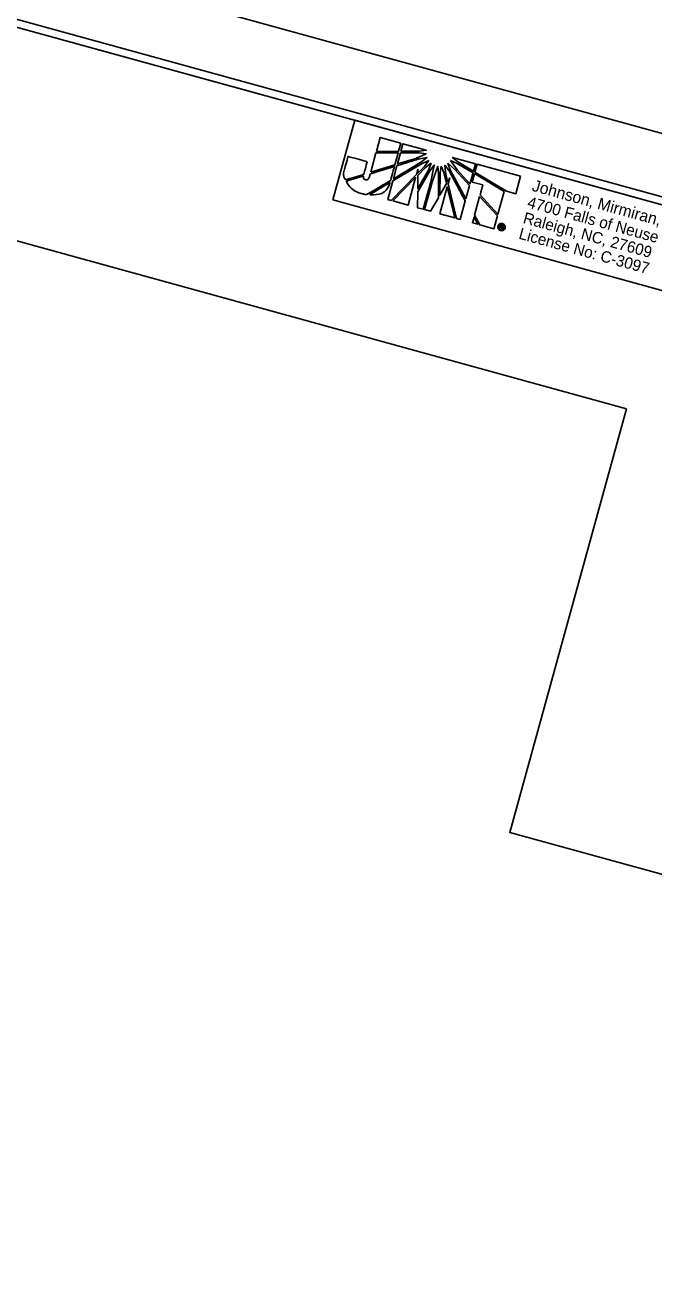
# Model space of a CAD drawing. Extents: x 1641063 to 2864602, y 841295 to 973236.
# Drawn here: x 1642637.9 to 1642843.9, y 842046.5 to 842457.9 of the extents above; entities that cross this region are included whole.
import ezdxf

# ---------------------------------------------------------------- set-up
doc = ezdxf.new("R2010")
doc.units = 0
for name, color, linetype in [('Old_Level_4', 7, 'Continuous'), ('Prop CMT Concrete Structures', 7, 'Continuous'), ('Prop CMT Guardrail Widen Shoulder', 7, 'Continuous'), ('Prop Dimension Text', 7, 'Continuous'), ('Prop PHM Wetland Impact Area Boundary Line', 7, 'Continuous')]:
    doc.layers.add(name, color=color, linetype=linetype)

msp = doc.modelspace()

# ---------------------------------------------------------------- linework, layer by layer
at = {"layer": 'Old_Level_4'}
msp.add_lwpolyline([(1641192.11, 841741.99), (1642815.27, 841295.31), (1643105.8, 842351.06), (1641482.64, 842797.74)], close=True, dxfattribs=at)
msp.add_lwpolyline([(1641192.11, 841741.99), (1642815.27, 841295.31), (1643105.8, 842351.06), (1641482.64, 842797.74)], close=True, dxfattribs=at)
at = {"layer": 'Prop CMT Concrete Structures'}
for points in [[(1643083.47, 842333.88), (1641637.2, 842731.89), (1641358.6, 841719.52), (1642804.85, 841321.52)], [(1641358.6, 841719.52), (1641637.16, 842731.87), (1642890.57, 842386.98), (1642850.76, 842242.29), (1643043.63, 842189.2), (1642804.85, 841321.52)]]:
    msp.add_lwpolyline(points, close=True, dxfattribs=at)
at = {"layer": 'Prop CMT Guardrail Widen Shoulder'}
for p, q in [((1642754.19, 842421.06), (1642752.96, 842416.57)), ((1642760.96, 842419.21), (1642754.19, 842421.06)), ((1642752.96, 842416.57), (1642760.24, 842416.59)), ((1642760.24, 842416.59), (1642760.96, 842419.21)), ((1642761.67, 842419.05), (1642761.01, 842416.62)), ((1642761.01, 842416.62), (1642767.12, 842416.63)), ((1642769.3, 842416.96), (1642761.67, 842419.05)), ((1642767.12, 842416.63), (1642769.3, 842416.96)), ((1642752.82, 842416.06), (1642751.09, 842409.75)), ((1642760.11, 842416.1), (1642752.82, 842416.06)), ((1642767.91, 842412.64), (1642758.34, 842406.9)), ((1642758.54, 842407.62), (1642767.72, 842413.09)), ((1642759.03, 842412.18), (1642760.11, 842416.1)), ((1642766.59, 842413.97), (1642759.7, 842411.84)), ((1642760.87, 842416.1), (1642759.86, 842412.43)), ((1642759.86, 842412.43), (1642765.83, 842414.26)), ((1642766.97, 842416.11), (1642760.87, 842416.1)), ((1642765.83, 842414.26), (1642769.26, 842415.77)), ((1642769.53, 842414.56), (1642766.59, 842413.97)), ((1642769.26, 842415.77), (1642766.97, 842416.11)), ((1642767.72, 842413.09), (1642769.53, 842414.56)), ((1642770.09, 842413.53), (1642767.91, 842412.64)), ((1642768.66, 842411.59), (1642770.09, 842413.53)), ((1642770.89, 842412.66), (1642769.08, 842411.31)), ((1642770.13, 842410.63), (1642770.89, 842412.66)), ((1642776.35, 842412.69), (1642777.15, 842410.47)), ((1642778.61, 842410.67), (1642776.35, 842412.69)), ((1642777.23, 842413.58), (1642779.44, 842410.48)), ((1642779.25, 842412.74), (1642777.23, 842413.58)), ((1642785.42, 842412.5), (1642777.92, 842414.59)), ((1642777.92, 842414.59), (1642779.58, 842413.18)), ((1642784.61, 842409.55), (1642779.25, 842412.74)), ((1642779.58, 842413.18), (1642784.75, 842410.07)), ((1642784.75, 842410.07), (1642785.42, 842412.5)), ((1642785.95, 842412.39), (1642785.24, 842409.78)), ((1642800.19, 842408.49), (1642785.95, 842412.39)), ((1642751.09, 842409.75), (1642759.03, 842412.18)), ((1642757.78, 842400.45), (1642766.05, 842408.94)), ((1642759.7, 842411.84), (1642758.54, 842407.62)), ((1642766.05, 842408.94), (1642766.54, 842410.72)), ((1642770.41, 842410.14), (1642766.49, 842403.35)), ((1642766.52, 842404.35), (1642770.13, 842410.63)), ((1642766.55, 842408.71), (1642766.52, 842404.35)), ((1642766.54, 842409.4), (1642768.66, 842411.59)), ((1642766.54, 842410.72), (1642766.54, 842409.4)), ((1642769.08, 842411.31), (1642766.55, 842408.71)), ((1642771.93, 842412.06), (1642770.41, 842410.14)), ((1642770.75, 842406.64), (1642771.93, 842412.06)), ((1642773.04, 842411.75), (1642771.23, 842406.5)), ((1642773.34, 842409.34), (1642773.04, 842411.75)), ((1642773.25, 842401.37), (1642773.34, 842409.34)), ((1642773.84, 842409.53), (1642773.72, 842402.21)), ((1642774.21, 842411.76), (1642773.84, 842409.53)), ((1642775.05, 842409.68), (1642774.21, 842411.76)), ((1642775.93, 842406.02), (1642775.05, 842409.68)), ((1642775.34, 842412.09), (1642775.57, 842409.7)), ((1642776.76, 842410.22), (1642775.34, 842412.09)), ((1642775.57, 842409.7), (1642776.28, 842406.61)), ((1642782.04, 842400.34), (1642776.76, 842410.22)), ((1642777.15, 842410.47), (1642782.23, 842401.04)), ((1642783.42, 842405.37), (1642778.61, 842410.67)), ((1642779.44, 842410.48), (1642783.58, 842405.98)), ((1642783.58, 842405.98), (1642784.61, 842409.55)), ((1642785.09, 842409.25), (1642784.35, 842406.53)), ((1642785.11, 842409.3), (1642785.09, 842409.25)), ((1642794.78, 842403.43), (1642785.11, 842409.3)), ((1642785.24, 842409.78), (1642785.22, 842409.7)), ((1642785.22, 842409.7), (1642795.56, 842403.49)), ((1642798.59, 842402.66), (1642800.19, 842408.49)), ((1642758.34, 842406.9), (1642756.66, 842400.76)), ((1642765.78, 842407.96), (1642758.3, 842400.31)), ((1642763.35, 842398.92), (1642765.78, 842407.96)), ((1642768.28, 842397.61), (1642770.75, 842406.64)), ((1642771.23, 842406.5), (1642768.76, 842397.48)), ((1642773.72, 842402.21), (1642775.93, 842406.02)), ((1642776.19, 842404.91), (1642773.78, 842396.1)), ((1642778.62, 842394.77), (1642776.19, 842404.91)), ((1642776.28, 842406.61), (1642777, 842407.86)), ((1642777, 842407.86), (1642776.46, 842405.88)), ((1642776.46, 842405.88), (1642779.17, 842394.58)), ((1642782.23, 842401.04), (1642783.42, 842405.37)), ((1642784.35, 842406.53), (1642787.82, 842405.57)), ((1642787.82, 842405.57), (1642786.93, 842402.32)), ((1642756.66, 842400.76), (1642757.78, 842400.45)), ((1642758.3, 842400.31), (1642763.35, 842398.92)), ((1642766.49, 842403.35), (1642766.42, 842398.12)), ((1642770.64, 842396.96), (1642773.25, 842401.37)), ((1642780.37, 842394.26), (1642782.04, 842400.34)), ((1642786.78, 842401.76), (1642785.12, 842395.71)), ((1642792.58, 842395.43), (1642786.78, 842401.76)), ((1642786.93, 842402.32), (1642792.73, 842395.95)), ((1642792.73, 842395.95), (1642794.78, 842403.43)), ((1642795.56, 842403.49), (1642798.59, 842402.66)), ((1642766.42, 842398.12), (1642768.28, 842397.61)), ((1642768.76, 842397.48), (1642770.64, 842396.96)), ((1642773.78, 842396.1), (1642778.62, 842394.77)), ((1642779.17, 842394.58), (1642780.37, 842394.26)), ((1642784.94, 842395.05), (1642784.41, 842393.15)), ((1642784.41, 842393.15), (1642786.17, 842392.67)), ((1642786.17, 842392.67), (1642784.94, 842395.05)), ((1642785.12, 842395.71), (1642786.84, 842392.48)), ((1642786.84, 842392.48), (1642791.43, 842391.22)), ((1642791.43, 842391.22), (1642792.58, 842395.43)), ((1642793.39, 842391.37), (1642793.67, 842392.41)), ((1642793.67, 842392.41), (1642794.1, 842392.29)), ((1642793.85, 842392.15), (1642793.79, 842391.9)), ((1642793.79, 842391.9), (1642793.98, 842391.85)), ((1642794.04, 842392.1), (1642793.85, 842392.15)), ((1642793.98, 842391.85), (1642793.92, 842391.66)), ((1642793.92, 842391.66), (1642793.98, 842391.85)), ((1642793.98, 842391.85), (1642793.99, 842391.85)), ((1642794.1, 842392.29), (1642794.04, 842392.1)), ((1642794.04, 842392.1), (1642794.1, 842392.29)), ((1642794.07, 842392.09), (1642794.04, 842392.1)), ((1642794.1, 842392.29), (1642794.16, 842392.28)), ((1642794.26, 842392.91), (1642794.21, 842392.69)), ((1642794.21, 842392.69), (1642794.26, 842392.91)), ((1642793.62, 842391.31), (1642793.39, 842391.37)), ((1642793.74, 842391.71), (1642793.62, 842391.31)), ((1642793.7, 842390.85), (1642793.64, 842390.63)), ((1642793.64, 842390.63), (1642793.7, 842390.85)), ((1642793.65, 842390.63), (1642793.64, 842390.63)), ((1642793.7, 842390.85), (1642793.71, 842390.85)), ((1642793.92, 842391.66), (1642793.74, 842391.71)), ((1642793.93, 842391.66), (1642793.92, 842391.66))]:
    msp.add_line(p, q, dxfattribs=at)
msp.add_lwpolyline([(1642738.73, 842400.68), (1642883.38, 842360.88), (1642890.57, 842386.98), (1642745.92, 842426.79)], close=True, dxfattribs=at)
for points in [[(1642752.96, 842416.57), (1642760.24, 842416.59), (1642760.96, 842419.21), (1642754.19, 842421.06), (1642752.96, 842416.57)], [(1642767.12, 842416.63), (1642769.3, 842416.96), (1642761.67, 842419.05), (1642761.01, 842416.62), (1642767.12, 842416.63)], [(1642751.09, 842409.75), (1642759.03, 842412.18), (1642760.11, 842416.1), (1642752.82, 842416.06), (1642751.09, 842409.75)], [(1642770.09, 842413.53), (1642767.91, 842412.64), (1642758.34, 842406.9), (1642756.66, 842400.76), (1642757.78, 842400.45), (1642766.05, 842408.94), (1642766.54, 842410.72), (1642766.54, 842409.4), (1642768.66, 842411.59), (1642770.09, 842413.53)], [(1642759.7, 842411.84), (1642758.54, 842407.62), (1642767.72, 842413.09), (1642769.53, 842414.56), (1642766.59, 842413.97), (1642759.7, 842411.84)], [(1642760.87, 842416.1), (1642759.86, 842412.43), (1642765.83, 842414.26), (1642769.26, 842415.77), (1642766.97, 842416.11), (1642760.87, 842416.1)], [(1642770.89, 842412.66), (1642769.08, 842411.31), (1642766.55, 842408.71), (1642766.52, 842404.35), (1642770.13, 842410.63), (1642770.89, 842412.66)], [(1642776.35, 842412.69), (1642777.15, 842410.47), (1642782.23, 842401.04), (1642783.42, 842405.37), (1642778.61, 842410.67), (1642776.35, 842412.69)], [(1642777.23, 842413.58), (1642779.44, 842410.48), (1642783.58, 842405.98), (1642784.61, 842409.55), (1642779.25, 842412.74), (1642777.23, 842413.58)], [(1642779.58, 842413.18), (1642784.75, 842410.07), (1642785.42, 842412.5), (1642777.92, 842414.59), (1642779.58, 842413.18)], [(1642800.19, 842408.49), (1642785.95, 842412.39), (1642785.24, 842409.78), (1642785.22, 842409.7), (1642795.56, 842403.49), (1642798.59, 842402.66), (1642800.19, 842408.49)], [(1642770.41, 842410.14), (1642766.49, 842403.35), (1642766.42, 842398.12), (1642768.28, 842397.61), (1642770.75, 842406.64), (1642771.93, 842412.06), (1642770.41, 842410.14)], [(1642773.04, 842411.75), (1642771.23, 842406.5), (1642768.76, 842397.48), (1642770.64, 842396.96), (1642773.25, 842401.37), (1642773.34, 842409.34), (1642773.04, 842411.75)], [(1642774.21, 842411.76), (1642773.84, 842409.53), (1642773.72, 842402.21), (1642775.93, 842406.02), (1642775.05, 842409.68), (1642774.21, 842411.76)], [(1642775.34, 842412.09), (1642775.57, 842409.7), (1642776.28, 842406.61), (1642777, 842407.86), (1642776.46, 842405.88), (1642779.17, 842394.58), (1642780.37, 842394.26), (1642782.04, 842400.34), (1642776.76, 842410.22), (1642775.34, 842412.09)], [(1642785.11, 842409.3), (1642785.09, 842409.25), (1642784.35, 842406.53), (1642787.82, 842405.57), (1642786.93, 842402.32), (1642792.73, 842395.95), (1642794.78, 842403.43), (1642785.11, 842409.3)], [(1642758.3, 842400.31), (1642763.35, 842398.92), (1642765.78, 842407.96), (1642758.3, 842400.31)], [(1642773.78, 842396.1), (1642778.62, 842394.77), (1642776.19, 842404.91), (1642773.78, 842396.1)], [(1642786.78, 842401.76), (1642785.12, 842395.71), (1642786.84, 842392.48), (1642791.43, 842391.22), (1642792.58, 842395.43), (1642786.78, 842401.76), (1642786.78, 842401.76)], [(1642784.41, 842393.15), (1642784.41, 842393.15), (1642786.17, 842392.67), (1642784.94, 842395.05), (1642784.41, 842393.15)], [(1642794.33, 842391.38), (1642794.32, 842391.32), (1642794.32, 842391.28), (1642794.31, 842391.25), (1642794.3, 842391.12), (1642794.09, 842391.18)]]:
    msp.add_lwpolyline(points, dxfattribs=at)
for points, degree in [([(1642749.94, 842413.18), (1642749.94, 842413.18), (1642743.67, 842414.9), (1642743.67, 842414.9), (1642743.67, 842414.9), (1642742.6, 842410.98), (1642742.6, 842410.98), (1642742.6, 842410.98), (1642742.48, 842410.57), (1642742.48, 842410.57), (1642742.15, 842409.34), (1642742.28, 842408.26), (1642742.77, 842407.24), (1642742.77, 842407.24), (1642748.78, 842408.96), (1642748.8, 842409.04), (1642748.8, 842409.04), (1642749.94, 842413.18), (1642749.94, 842413.18)], 3), ([(1642749.36, 842407.27), (1642748.96, 842407.38), (1642748.68, 842407.7), (1642748.74, 842408.49), (1642748.74, 842408.49), (1642743.05, 842406.82), (1642743.05, 842406.82), (1642744.12, 842404.83), (1642746.25, 842403.24), (1642748.27, 842402.68), (1642748.8, 842402.54), (1642749.21, 842402.47), (1642749.8, 842402.43), (1642749.8, 842402.43), (1642757.63, 842407.06), (1642757.63, 842407.06), (1642757.63, 842407.06), (1642758.88, 842411.62), (1642758.88, 842411.62), (1642758.88, 842411.62), (1642750.93, 842409.18), (1642750.93, 842409.18), (1642750.46, 842407.47), (1642749.92, 842407.12), (1642749.36, 842407.27)], 3), ([(1642749.36, 842407.27), (1642748.96, 842407.38), (1642748.68, 842407.7), (1642748.74, 842408.49), (1642748.74, 842408.49), (1642743.05, 842406.82), (1642743.05, 842406.82), (1642744.12, 842404.83), (1642746.25, 842403.24), (1642748.27, 842402.68), (1642748.8, 842402.54), (1642749.21, 842402.47), (1642749.8, 842402.43), (1642749.8, 842402.43), (1642757.63, 842407.06), (1642757.63, 842407.06), (1642757.63, 842407.06), (1642758.88, 842411.62), (1642758.88, 842411.62), (1642758.88, 842411.62), (1642750.93, 842409.18), (1642750.93, 842409.18), (1642750.46, 842407.47), (1642749.92, 842407.12), (1642749.36, 842407.27)], 3), ([(1642757.44, 842406.35), (1642757.44, 842406.35), (1642750.67, 842402.35), (1642750.67, 842402.35), (1642753.43, 842402.28), (1642756.46, 842403.29), (1642757.44, 842406.35)], 3), ([(1642793.64, 842390.63), (1642793.33, 842390.71), (1642793.09, 842390.9), (1642792.92, 842391.19), (1642792.76, 842391.47), (1642792.72, 842391.77), (1642792.81, 842392.09), (1642792.89, 842392.41), (1642793.08, 842392.65), (1642793.37, 842392.8), (1642793.65, 842392.95), (1642793.94, 842392.99), (1642794.26, 842392.91)], 3), ([(1642794.21, 842392.69), (1642793.95, 842392.76), (1642793.71, 842392.73), (1642793.49, 842392.61), (1642793.26, 842392.48), (1642793.1, 842392.28), (1642793.03, 842392.03), (1642792.96, 842391.77), (1642793, 842391.52), (1642793.13, 842391.3), (1642793.25, 842391.07), (1642793.45, 842390.92), (1642793.7, 842390.85)], 3), ([(1642793.71, 842390.85), (1642793.97, 842390.78), (1642794.21, 842390.81), (1642794.43, 842390.94), (1642794.66, 842391.07), (1642794.82, 842391.27), (1642794.89, 842391.52), (1642794.96, 842391.77), (1642794.92, 842392.03), (1642794.79, 842392.25), (1642794.66, 842392.47), (1642794.47, 842392.62), (1642794.21, 842392.69)], 3), ([(1642793.99, 842391.85), (1642794.14, 842391.81), (1642794.22, 842391.83), (1642794.25, 842391.92), (1642794.27, 842391.99), (1642794.21, 842392.05), (1642794.07, 842392.09)], 3), ([(1642794.16, 842392.28), (1642794.43, 842392.2), (1642794.53, 842392.06), (1642794.47, 842391.86), (1642794.45, 842391.76), (1642794.39, 842391.7), (1642794.29, 842391.66)], 3), ([(1642794.26, 842392.91), (1642794.58, 842392.82), (1642794.83, 842392.63), (1642794.99, 842392.35), (1642795.16, 842392.08), (1642795.2, 842391.78), (1642795.11, 842391.46)], 3), ([(1642795.11, 842391.46), (1642795.02, 842391.14), (1642794.84, 842390.9), (1642794.56, 842390.73), (1642794.27, 842390.58), (1642793.97, 842390.54), (1642793.65, 842390.63)], 3), ([(1642794.1, 842391.57), (1642794.08, 842391.6), (1642794.03, 842391.63), (1642793.93, 842391.66)], 2), ([(1642794.09, 842391.18), (1642794.07, 842391.25), (1642794.07, 842391.31), (1642794.09, 842391.38), (1642794.12, 842391.48), (1642794.12, 842391.54), (1642794.1, 842391.57)], 3), ([(1642794.29, 842391.66), (1642794.34, 842391.61), (1642794.36, 842391.51), (1642794.33, 842391.38)], 2)]:
    msp.add_open_spline(points, degree=degree, dxfattribs=at)
at = {"layer": 'Prop Dimension Text'}
msp.add_lwpolyline([(1641209.95, 841757.82), (1642816.23, 841315.8), (1643096.16, 842332.97), (1641489.87, 842775.01)], close=True, dxfattribs=at)
at = {"layer": 'Prop PHM Wetland Impact Area Boundary Line'}
for points in [[(1642834.84, 842332.26), (1642796.64, 842193.46), (1642979.12, 842143.25), (1642931.91, 841980.78), (1642684.68, 842016.94), (1642616.55, 841780.17), (1642867.94, 841712.2), (1642769.91, 841383), (1642620.74, 841424.05), (1642612.78, 841395.12), (1641412.11, 841725.54), (1641476.31, 841958.82), (1641627.07, 841958.82), (1641755.49, 842119.21), (1641752.38, 842181.83), (1641796.56, 842667.29)], [(1642584.62, 842450.42), (1642572.01, 842404.59), (1642834.84, 842332.26)]]:
    msp.add_lwpolyline(points, dxfattribs=at)

# ---------------------------------------------------------------- texts
at = {"layer": 'Prop CMT Guardrail Widen Shoulder'}
for s, height, p in [('Johnson, Mirmiran, & Thompson Inc.', 3.8334, (1642803.65, 842403.71)), ('4700 Falls of Neuse Rd, Suite 100, ', 3.7239, (1642802.15, 842398.28)), ('Raleigh, NC, 27609', 3.7239, (1642800.74, 842393.15)), ('License No: C-3097', 3.7239, (1642799.33, 842388.02))]:
    msp.add_text(s, height=height, rotation=344.6135, dxfattribs=at).set_placement(p)

doc.saveas('drawing.dxf')
